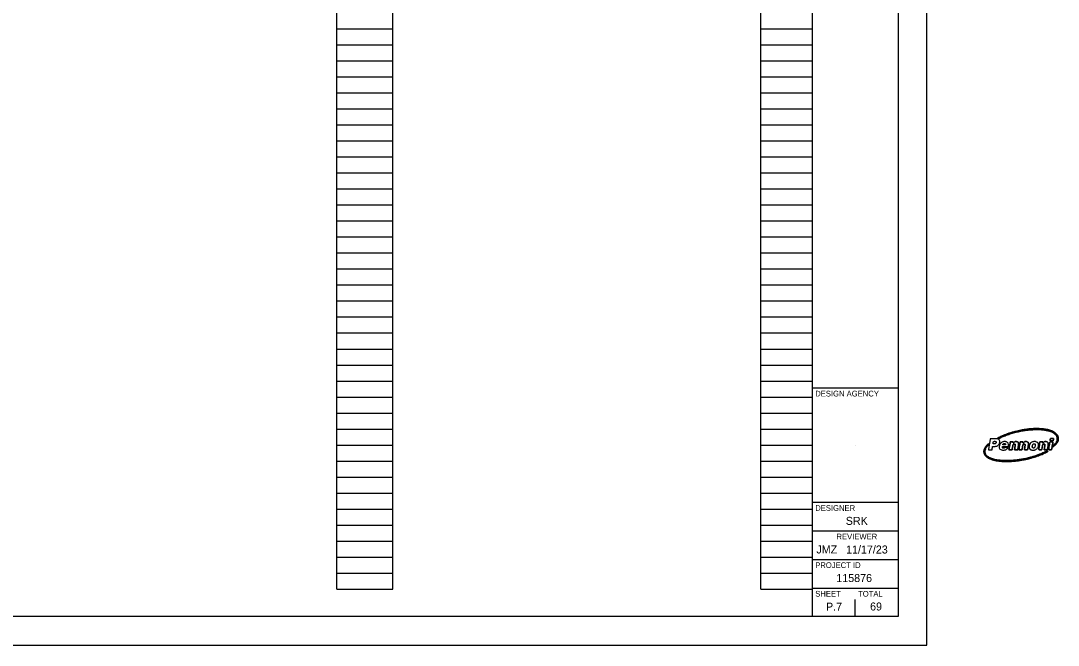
# Model space of a CAD drawing. Extents: x 0 to 36.3, y 0 to 22.
# Drawn here: x 18.15 to 36.3, y 0 to 10.92 of the extents above; entities that cross this region are included whole.
import ezdxf

# ---------------------------------------------------------------- set-up
doc = ezdxf.new("R2010")
doc.units = 0
for name, color, linetype in [('SH_Border', 7, 'Continuous'), ('SH_Cut_Line', 7, 'Continuous'), ('SH_Data', 7, 'Continuous')]:
    doc.layers.add(name, color=color, linetype=linetype)

msp = doc.modelspace()

# ---------------------------------------------------------------- linework, layer by layer
at = {"layer": 'SH_Border'}
for p, q in [((32, 0.5), (32, 21.5)), ((32, 4.5), (33.5, 4.5)), ((35.381, 3.503), (35.331, 3.503)), ((32, 2.5), (33.5, 2.5)), ((32, 2), (33.5, 2)), ((32, 1.5), (33.5, 1.5)), ((32, 1), (33.5, 1))]:
    msp.add_line(p, q, dxfattribs=at)
msp.add_lwpolyline([(1.5, 21.5), (33.5, 21.5), (33.5, 0.5), (1.5, 0.5)], close=True, dxfattribs=at)
for points, degree in [([(35.24, 3.621), (35.247, 3.619), (35.253, 3.616), (35.259, 3.615), (35.261, 3.614), (35.264, 3.614), (35.266, 3.615), (35.295, 3.629), (35.323, 3.643), (35.352, 3.655), (35.393, 3.673), (35.436, 3.688), (35.479, 3.701), (35.521, 3.714), (35.563, 3.725), (35.606, 3.734), (35.646, 3.743), (35.686, 3.751), (35.726, 3.756), (35.758, 3.76), (35.79, 3.764), (35.822, 3.767), (35.847, 3.769), (35.873, 3.77), (35.898, 3.771), (35.953, 3.772), (36.008, 3.77), (36.063, 3.762), (36.092, 3.758), (36.122, 3.752), (36.15, 3.742), (36.186, 3.731), (36.219, 3.717), (36.247, 3.691), (36.262, 3.678), (36.274, 3.661), (36.279, 3.641), (36.284, 3.624), (36.286, 3.607), (36.283, 3.589), (36.279, 3.569), (36.269, 3.552), (36.257, 3.536), (36.245, 3.521), (36.231, 3.508), (36.216, 3.495), (36.214, 3.494), (36.213, 3.492), (36.212, 3.49), (36.211, 3.485), (36.21, 3.479), (36.209, 3.473), (36.209, 3.471), (36.208, 3.469), (36.208, 3.465), (36.232, 3.485), (36.255, 3.505), (36.273, 3.529), (36.282, 3.54), (36.29, 3.553), (36.295, 3.566), (36.302, 3.585), (36.302, 3.604), (36.3, 3.623), (36.296, 3.658), (36.28, 3.685), (36.254, 3.708), (36.23, 3.728), (36.203, 3.741), (36.173, 3.752), (36.136, 3.766), (36.098, 3.774), (36.059, 3.779), (36.024, 3.784), (35.989, 3.787), (35.953, 3.788), (35.897, 3.789), (35.841, 3.787), (35.785, 3.781), (35.754, 3.777), (35.723, 3.773), (35.692, 3.768), (35.647, 3.761), (35.602, 3.752), (35.558, 3.74), (35.497, 3.725), (35.438, 3.707), (35.379, 3.684), (35.339, 3.669), (35.299, 3.651), (35.26, 3.631), (35.253, 3.628), (35.247, 3.625), (35.24, 3.621)], 3), ([(35.24, 3.621), (35.247, 3.625), (35.253, 3.628), (35.26, 3.631), (35.299, 3.651), (35.339, 3.669), (35.379, 3.684), (35.438, 3.707), (35.497, 3.725), (35.558, 3.74), (35.602, 3.752), (35.647, 3.761), (35.692, 3.768), (35.723, 3.773), (35.754, 3.777), (35.785, 3.781), (35.841, 3.787), (35.897, 3.789), (35.953, 3.788), (35.989, 3.787), (36.024, 3.784), (36.059, 3.779), (36.098, 3.774), (36.136, 3.766), (36.173, 3.752), (36.203, 3.741), (36.23, 3.728), (36.254, 3.708), (36.28, 3.685), (36.296, 3.658), (36.3, 3.623), (36.302, 3.604), (36.302, 3.585), (36.295, 3.566), (36.29, 3.553), (36.282, 3.54), (36.273, 3.529), (36.255, 3.505), (36.232, 3.485), (36.208, 3.465), (36.208, 3.469), (36.209, 3.471), (36.209, 3.473), (36.21, 3.479), (36.211, 3.485), (36.212, 3.49), (36.213, 3.492), (36.214, 3.494), (36.216, 3.495), (36.231, 3.508), (36.245, 3.521), (36.257, 3.536), (36.269, 3.552), (36.279, 3.569), (36.283, 3.589), (36.286, 3.607), (36.284, 3.624), (36.279, 3.641), (36.274, 3.661), (36.262, 3.678), (36.247, 3.691), (36.219, 3.717), (36.186, 3.731), (36.15, 3.742), (36.122, 3.752), (36.092, 3.758), (36.063, 3.762), (36.008, 3.77), (35.953, 3.772), (35.898, 3.771), (35.873, 3.77), (35.847, 3.769), (35.822, 3.767), (35.79, 3.764), (35.758, 3.76), (35.726, 3.756), (35.686, 3.751), (35.646, 3.743), (35.606, 3.734), (35.563, 3.725), (35.521, 3.714), (35.479, 3.701), (35.436, 3.688), (35.393, 3.673), (35.352, 3.655), (35.323, 3.643), (35.295, 3.629), (35.266, 3.615), (35.264, 3.614), (35.261, 3.614), (35.259, 3.615), (35.253, 3.616), (35.247, 3.619), (35.24, 3.621)], 3), ([(36.128, 3.392), (36.128, 3.392), (36.128, 3.393), (36.128, 3.393), (36.118, 3.393), (36.108, 3.393), (36.098, 3.393), (36.096, 3.393), (36.093, 3.392), (36.091, 3.391), (36.053, 3.372), (36.015, 3.355), (35.976, 3.34), (35.918, 3.317), (35.859, 3.298), (35.799, 3.283), (35.756, 3.271), (35.713, 3.262), (35.669, 3.254), (35.644, 3.25), (35.619, 3.246), (35.594, 3.242), (35.569, 3.239), (35.543, 3.236), (35.518, 3.234), (35.493, 3.232), (35.469, 3.23), (35.445, 3.23), (35.417, 3.229), (35.389, 3.228), (35.361, 3.229), (35.33, 3.231), (35.299, 3.233), (35.268, 3.236), (35.23, 3.24), (35.192, 3.248), (35.156, 3.259), (35.124, 3.269), (35.094, 3.282), (35.067, 3.302), (35.051, 3.314), (35.036, 3.329), (35.027, 3.348), (35.015, 3.374), (35.016, 3.4), (35.027, 3.427), (35.036, 3.45), (35.05, 3.47), (35.067, 3.488), (35.072, 3.494), (35.078, 3.5), (35.078, 3.509), (35.079, 3.514), (35.08, 3.52), (35.081, 3.526), (35.08, 3.525), (35.079, 3.525), (35.078, 3.524), (35.069, 3.514), (35.059, 3.505), (35.05, 3.494), (35.03, 3.472), (35.015, 3.448), (35.006, 3.419), (35.002, 3.402), (35, 3.385), (35.003, 3.368), (35.008, 3.341), (35.023, 3.319), (35.042, 3.301), (35.065, 3.28), (35.092, 3.266), (35.12, 3.254), (35.167, 3.235), (35.217, 3.225), (35.267, 3.219), (35.297, 3.216), (35.329, 3.214), (35.36, 3.212), (35.402, 3.211), (35.444, 3.211), (35.486, 3.215), (35.521, 3.217), (35.555, 3.221), (35.589, 3.225), (35.62, 3.229), (35.65, 3.234), (35.681, 3.239), (35.735, 3.249), (35.789, 3.261), (35.842, 3.276), (35.887, 3.289), (35.932, 3.304), (35.976, 3.321), (36.019, 3.338), (36.061, 3.356), (36.102, 3.377), (36.111, 3.382), (36.119, 3.387), (36.128, 3.392)], 3), ([(36.128, 3.392), (36.119, 3.387), (36.111, 3.382), (36.102, 3.377), (36.061, 3.356), (36.019, 3.338), (35.976, 3.321), (35.932, 3.304), (35.887, 3.289), (35.842, 3.276), (35.789, 3.261), (35.735, 3.249), (35.681, 3.239), (35.65, 3.234), (35.62, 3.229), (35.589, 3.225), (35.555, 3.221), (35.521, 3.217), (35.486, 3.215), (35.444, 3.211), (35.402, 3.211), (35.36, 3.212), (35.329, 3.214), (35.297, 3.216), (35.267, 3.219), (35.217, 3.225), (35.167, 3.235), (35.12, 3.254), (35.092, 3.266), (35.065, 3.28), (35.042, 3.301), (35.023, 3.319), (35.008, 3.341), (35.003, 3.368), (35, 3.385), (35.002, 3.402), (35.006, 3.419), (35.015, 3.448), (35.03, 3.472), (35.05, 3.494), (35.059, 3.505), (35.069, 3.514), (35.078, 3.524), (35.079, 3.525), (35.08, 3.525), (35.081, 3.526), (35.08, 3.52), (35.079, 3.514), (35.078, 3.509), (35.078, 3.5), (35.072, 3.494), (35.067, 3.488), (35.05, 3.47), (35.036, 3.45), (35.027, 3.427), (35.016, 3.4), (35.015, 3.374), (35.027, 3.348), (35.036, 3.329), (35.051, 3.314), (35.067, 3.302), (35.094, 3.282), (35.124, 3.269), (35.156, 3.259), (35.192, 3.248), (35.23, 3.24), (35.268, 3.236), (35.299, 3.233), (35.33, 3.231), (35.361, 3.229), (35.389, 3.228), (35.417, 3.229), (35.445, 3.23), (35.469, 3.23), (35.493, 3.232), (35.518, 3.234), (35.543, 3.236), (35.569, 3.239), (35.594, 3.242), (35.619, 3.246), (35.644, 3.25), (35.669, 3.254), (35.713, 3.262), (35.756, 3.271), (35.799, 3.283), (35.859, 3.298), (35.918, 3.317), (35.976, 3.34), (36.015, 3.355), (36.053, 3.372), (36.091, 3.391), (36.093, 3.392), (36.096, 3.393), (36.098, 3.393), (36.108, 3.393), (36.118, 3.393), (36.128, 3.393), (36.128, 3.393), (36.128, 3.392), (36.128, 3.392)], 3), ([(35.252, 3.602), (35.239, 3.608), (35.226, 3.61), (35.212, 3.61), (35.18, 3.611), (35.148, 3.61), (35.117, 3.61), (35.115, 3.61), (35.114, 3.61), (35.113, 3.608), (35.109, 3.586), (35.106, 3.565), (35.102, 3.543), (35.096, 3.509), (35.09, 3.474), (35.084, 3.439), (35.082, 3.432), (35.081, 3.424), (35.08, 3.417)], 3), ([(35.08, 3.417), (35.081, 3.417), (35.081, 3.417), (35.082, 3.417), (35.101, 3.417), (35.121, 3.417), (35.14, 3.417), (35.143, 3.417), (35.143, 3.418), (35.143, 3.42), (35.145, 3.431), (35.147, 3.442), (35.149, 3.454), (35.151, 3.461), (35.152, 3.469), (35.153, 3.477)], 3), ([(35.153, 3.477), (35.161, 3.477), (35.168, 3.477), (35.175, 3.477), (35.188, 3.477), (35.201, 3.477), (35.213, 3.48), (35.23, 3.483), (35.245, 3.49), (35.257, 3.502), (35.272, 3.518), (35.278, 3.537), (35.278, 3.559), (35.279, 3.578), (35.27, 3.593), (35.252, 3.602)], 3), ([(35.161, 3.522), (35.164, 3.536), (35.166, 3.55), (35.168, 3.563), (35.169, 3.564), (35.17, 3.565), (35.171, 3.565), (35.182, 3.565), (35.194, 3.567), (35.205, 3.563), (35.215, 3.56), (35.219, 3.554), (35.217, 3.543)], 3), ([(35.217, 3.543), (35.215, 3.531), (35.206, 3.523), (35.193, 3.522), (35.183, 3.522), (35.172, 3.522), (35.161, 3.522)], 3), ([(35.433, 3.508), (35.429, 3.533), (35.416, 3.55), (35.392, 3.557), (35.379, 3.562), (35.365, 3.562), (35.352, 3.561), (35.33, 3.558), (35.311, 3.549), (35.295, 3.532), (35.281, 3.517), (35.273, 3.5), (35.271, 3.479), (35.268, 3.45), (35.28, 3.426), (35.309, 3.417), (35.325, 3.412), (35.342, 3.411), (35.358, 3.414), (35.376, 3.416), (35.392, 3.422), (35.406, 3.434), (35.414, 3.441), (35.42, 3.449), (35.424, 3.459)], 3), ([(35.424, 3.459), (35.407, 3.459), (35.39, 3.459), (35.373, 3.458), (35.372, 3.458), (35.371, 3.457), (35.37, 3.457), (35.366, 3.454), (35.362, 3.45), (35.358, 3.448), (35.341, 3.442), (35.324, 3.451), (35.325, 3.47), (35.325, 3.474), (35.326, 3.475), (35.33, 3.475), (35.362, 3.475), (35.394, 3.475), (35.427, 3.475), (35.428, 3.475), (35.43, 3.475), (35.432, 3.475)], 3), ([(35.331, 3.503), (35.332, 3.515), (35.342, 3.525), (35.354, 3.527), (35.36, 3.528), (35.366, 3.528), (35.371, 3.525), (35.379, 3.521), (35.383, 3.513), (35.381, 3.503)], 3), ([(35.432, 3.475), (35.434, 3.486), (35.435, 3.497), (35.433, 3.508)], 2), ([(35.439, 3.416), (35.439, 3.415), (35.44, 3.415), (35.441, 3.415), (35.458, 3.415), (35.475, 3.415), (35.492, 3.415), (35.494, 3.415), (35.494, 3.416), (35.495, 3.418), (35.496, 3.426), (35.497, 3.435), (35.499, 3.443), (35.502, 3.46), (35.505, 3.478), (35.509, 3.495), (35.511, 3.505), (35.515, 3.513), (35.525, 3.515), (35.538, 3.519), (35.552, 3.516), (35.55, 3.497), (35.548, 3.482), (35.545, 3.468), (35.543, 3.454), (35.541, 3.441), (35.538, 3.428), (35.536, 3.416), (35.537, 3.415), (35.537, 3.415), (35.538, 3.415), (35.555, 3.415), (35.572, 3.415), (35.589, 3.415), (35.591, 3.415), (35.592, 3.416), (35.592, 3.419), (35.596, 3.442), (35.601, 3.466), (35.605, 3.49), (35.607, 3.502), (35.609, 3.515), (35.607, 3.527), (35.605, 3.543), (35.596, 3.554), (35.58, 3.558), (35.559, 3.564), (35.539, 3.56), (35.522, 3.545), (35.518, 3.542), (35.514, 3.538), (35.51, 3.535), (35.512, 3.542), (35.513, 3.549), (35.514, 3.557), (35.498, 3.557), (35.481, 3.557), (35.465, 3.556), (35.464, 3.556), (35.463, 3.555), (35.463, 3.554), (35.462, 3.55), (35.461, 3.545), (35.461, 3.541), (35.455, 3.511), (35.45, 3.48), (35.445, 3.45), (35.443, 3.438), (35.441, 3.427), (35.439, 3.416)], 3), ([(35.439, 3.416), (35.441, 3.427), (35.443, 3.438), (35.445, 3.45), (35.45, 3.48), (35.455, 3.511), (35.461, 3.541), (35.461, 3.545), (35.462, 3.55), (35.463, 3.554), (35.463, 3.555), (35.464, 3.556), (35.465, 3.556), (35.481, 3.557), (35.498, 3.557), (35.514, 3.557), (35.513, 3.549), (35.512, 3.542), (35.51, 3.535), (35.514, 3.538), (35.518, 3.542), (35.522, 3.545), (35.539, 3.56), (35.559, 3.564), (35.58, 3.558), (35.596, 3.554), (35.605, 3.543), (35.607, 3.527), (35.609, 3.515), (35.607, 3.502), (35.605, 3.49), (35.601, 3.466), (35.596, 3.442), (35.592, 3.419), (35.592, 3.416), (35.591, 3.415), (35.589, 3.415), (35.572, 3.415), (35.555, 3.415), (35.538, 3.415), (35.537, 3.415), (35.537, 3.415), (35.536, 3.416), (35.538, 3.428), (35.541, 3.441), (35.543, 3.454), (35.545, 3.468), (35.548, 3.482), (35.55, 3.497), (35.552, 3.516), (35.538, 3.519), (35.525, 3.515), (35.515, 3.513), (35.511, 3.505), (35.509, 3.495), (35.505, 3.478), (35.502, 3.46), (35.499, 3.443), (35.497, 3.435), (35.496, 3.426), (35.495, 3.418), (35.494, 3.416), (35.494, 3.415), (35.492, 3.415), (35.475, 3.415), (35.458, 3.415), (35.441, 3.415), (35.44, 3.415), (35.439, 3.415), (35.439, 3.416)], 3), ([(35.612, 3.416), (35.612, 3.415), (35.612, 3.415), (35.613, 3.415), (35.63, 3.415), (35.647, 3.415), (35.665, 3.415), (35.666, 3.415), (35.667, 3.417), (35.668, 3.418), (35.671, 3.435), (35.674, 3.452), (35.677, 3.469), (35.679, 3.479), (35.68, 3.49), (35.683, 3.5), (35.687, 3.513), (35.699, 3.519), (35.712, 3.516), (35.718, 3.515), (35.721, 3.511), (35.722, 3.505), (35.723, 3.502), (35.723, 3.499), (35.723, 3.496), (35.721, 3.485), (35.719, 3.473), (35.717, 3.462), (35.715, 3.447), (35.712, 3.431), (35.709, 3.416), (35.71, 3.415), (35.71, 3.415), (35.71, 3.415), (35.727, 3.415), (35.745, 3.415), (35.762, 3.415), (35.763, 3.415), (35.765, 3.417), (35.765, 3.418), (35.769, 3.441), (35.773, 3.463), (35.777, 3.485), (35.779, 3.497), (35.781, 3.509), (35.781, 3.522), (35.781, 3.537), (35.775, 3.55), (35.759, 3.556), (35.739, 3.564), (35.719, 3.562), (35.701, 3.55), (35.695, 3.545), (35.689, 3.54), (35.683, 3.535), (35.685, 3.543), (35.686, 3.549), (35.687, 3.557), (35.671, 3.557), (35.655, 3.557), (35.639, 3.557), (35.636, 3.557), (35.636, 3.555), (35.636, 3.553), (35.632, 3.529), (35.627, 3.505), (35.623, 3.481), (35.619, 3.46), (35.616, 3.438), (35.612, 3.416)], 3), ([(35.612, 3.416), (35.616, 3.438), (35.619, 3.46), (35.623, 3.481), (35.627, 3.505), (35.632, 3.529), (35.636, 3.553), (35.636, 3.555), (35.636, 3.557), (35.639, 3.557), (35.655, 3.557), (35.671, 3.557), (35.687, 3.557), (35.686, 3.549), (35.685, 3.543), (35.683, 3.535), (35.689, 3.54), (35.695, 3.545), (35.701, 3.55), (35.719, 3.562), (35.739, 3.564), (35.759, 3.556), (35.775, 3.55), (35.781, 3.537), (35.781, 3.522), (35.781, 3.509), (35.779, 3.497), (35.777, 3.485), (35.773, 3.463), (35.769, 3.441), (35.765, 3.418), (35.765, 3.417), (35.763, 3.415), (35.762, 3.415), (35.745, 3.415), (35.727, 3.415), (35.71, 3.415), (35.71, 3.415), (35.71, 3.415), (35.709, 3.416), (35.712, 3.431), (35.715, 3.447), (35.717, 3.462), (35.719, 3.473), (35.721, 3.485), (35.723, 3.496), (35.723, 3.499), (35.723, 3.502), (35.722, 3.505), (35.721, 3.511), (35.718, 3.515), (35.712, 3.516), (35.699, 3.519), (35.687, 3.513), (35.683, 3.5), (35.68, 3.49), (35.679, 3.479), (35.677, 3.469), (35.674, 3.452), (35.671, 3.435), (35.668, 3.418), (35.667, 3.417), (35.666, 3.415), (35.665, 3.415), (35.647, 3.415), (35.63, 3.415), (35.613, 3.415), (35.612, 3.415), (35.612, 3.415), (35.612, 3.416)], 3), ([(35.955, 3.508), (35.953, 3.53), (35.942, 3.545), (35.922, 3.554), (35.903, 3.562), (35.883, 3.562), (35.863, 3.558), (35.839, 3.553), (35.82, 3.541), (35.806, 3.52), (35.805, 3.518), (35.804, 3.515), (35.803, 3.513), (35.802, 3.511), (35.801, 3.509), (35.8, 3.507), (35.795, 3.496), (35.792, 3.484), (35.792, 3.472), (35.792, 3.47), (35.792, 3.467), (35.792, 3.465), (35.792, 3.457), (35.794, 3.45), (35.797, 3.444), (35.797, 3.443), (35.798, 3.441), (35.798, 3.44), (35.799, 3.439), (35.8, 3.438), (35.8, 3.437), (35.803, 3.434), (35.805, 3.43), (35.809, 3.427), (35.811, 3.426), (35.813, 3.424), (35.815, 3.423), (35.815, 3.422), (35.816, 3.422), (35.817, 3.422), (35.818, 3.421), (35.819, 3.42), (35.82, 3.42), (35.822, 3.419), (35.824, 3.418), (35.826, 3.417), (35.837, 3.412), (35.849, 3.411), (35.861, 3.41)], 3), ([(35.848, 3.471), (35.849, 3.487), (35.851, 3.501), (35.86, 3.513), (35.865, 3.519), (35.872, 3.523), (35.88, 3.523), (35.889, 3.523), (35.895, 3.52), (35.897, 3.511), (35.898, 3.505), (35.899, 3.498), (35.899, 3.491)], 3), ([(35.899, 3.491), (35.898, 3.481), (35.895, 3.471), (35.89, 3.462), (35.884, 3.452), (35.874, 3.447), (35.864, 3.449), (35.857, 3.45), (35.852, 3.453), (35.85, 3.459), (35.849, 3.464), (35.848, 3.469), (35.848, 3.471)], 3), ([(35.861, 3.41), (35.868, 3.411), (35.875, 3.412), (35.882, 3.413), (35.901, 3.416), (35.918, 3.425), (35.931, 3.439), (35.949, 3.459), (35.956, 3.482), (35.955, 3.508)], 3), ([(35.982, 3.556), (35.974, 3.509), (35.966, 3.462), (35.958, 3.415), (35.977, 3.415), (35.995, 3.415), (36.013, 3.415), (36.016, 3.43), (36.018, 3.444), (36.021, 3.458), (36.023, 3.471), (36.025, 3.484), (36.028, 3.496), (36.031, 3.51), (36.041, 3.517), (36.054, 3.517), (36.063, 3.516), (36.068, 3.511), (36.069, 3.503), (36.069, 3.5), (36.069, 3.497), (36.069, 3.494), (36.066, 3.475), (36.062, 3.456), (36.059, 3.437), (36.058, 3.43), (36.057, 3.423), (36.055, 3.415), (36.074, 3.415), (36.092, 3.415), (36.111, 3.415), (36.111, 3.417), (36.111, 3.418), (36.111, 3.419), (36.115, 3.44), (36.119, 3.462), (36.123, 3.483), (36.125, 3.497), (36.128, 3.51), (36.127, 3.525), (36.126, 3.541), (36.117, 3.553), (36.101, 3.558), (36.076, 3.565), (36.055, 3.559), (36.036, 3.541), (36.034, 3.539), (36.032, 3.537), (36.03, 3.535), (36.03, 3.535), (36.03, 3.535), (36.03, 3.536), (36.031, 3.542), (36.032, 3.549), (36.033, 3.556), (36.016, 3.556), (35.999, 3.556), (35.982, 3.556)], 3), ([(35.982, 3.556), (35.999, 3.556), (36.016, 3.556), (36.033, 3.556), (36.032, 3.549), (36.031, 3.542), (36.03, 3.536), (36.03, 3.535), (36.03, 3.535), (36.03, 3.535), (36.032, 3.537), (36.034, 3.539), (36.036, 3.541), (36.055, 3.559), (36.076, 3.565), (36.101, 3.558), (36.117, 3.553), (36.126, 3.541), (36.127, 3.525), (36.128, 3.51), (36.125, 3.497), (36.123, 3.483), (36.119, 3.462), (36.115, 3.44), (36.111, 3.419), (36.111, 3.418), (36.111, 3.417), (36.111, 3.415), (36.092, 3.415), (36.074, 3.415), (36.055, 3.415), (36.057, 3.423), (36.058, 3.43), (36.059, 3.437), (36.062, 3.456), (36.066, 3.475), (36.069, 3.494), (36.069, 3.497), (36.069, 3.5), (36.069, 3.503), (36.068, 3.511), (36.063, 3.516), (36.054, 3.517), (36.041, 3.517), (36.031, 3.51), (36.028, 3.496), (36.025, 3.484), (36.023, 3.471), (36.021, 3.458), (36.018, 3.444), (36.016, 3.43), (36.013, 3.415), (35.995, 3.415), (35.977, 3.415), (35.958, 3.415), (35.966, 3.462), (35.974, 3.509), (35.982, 3.556)], 3), ([(36.185, 3.417), (36.167, 3.417), (36.149, 3.417), (36.13, 3.417), (36.138, 3.464), (36.146, 3.51), (36.154, 3.557), (36.173, 3.557), (36.191, 3.557), (36.21, 3.557), (36.202, 3.51), (36.193, 3.464), (36.185, 3.417)], 3), ([(36.185, 3.417), (36.193, 3.464), (36.202, 3.51), (36.21, 3.557), (36.191, 3.557), (36.173, 3.557), (36.154, 3.557), (36.146, 3.51), (36.138, 3.464), (36.13, 3.417), (36.149, 3.417), (36.167, 3.417), (36.185, 3.417)], 3), ([(36.22, 3.615), (36.218, 3.603), (36.216, 3.591), (36.213, 3.578), (36.213, 3.577), (36.212, 3.576), (36.211, 3.576), (36.193, 3.576), (36.176, 3.576), (36.158, 3.576), (36.159, 3.586), (36.161, 3.595), (36.163, 3.604), (36.163, 3.606), (36.164, 3.609), (36.164, 3.611), (36.164, 3.615), (36.165, 3.615), (36.169, 3.615), (36.185, 3.615), (36.2, 3.615), (36.216, 3.615), (36.217, 3.615), (36.218, 3.615), (36.22, 3.615)], 3), ([(36.22, 3.615), (36.218, 3.615), (36.217, 3.615), (36.216, 3.615), (36.2, 3.615), (36.185, 3.615), (36.169, 3.615), (36.165, 3.615), (36.164, 3.615), (36.164, 3.611), (36.164, 3.609), (36.163, 3.606), (36.163, 3.604), (36.161, 3.595), (36.159, 3.586), (36.158, 3.576), (36.176, 3.576), (36.193, 3.576), (36.211, 3.576), (36.212, 3.576), (36.213, 3.577), (36.213, 3.578), (36.216, 3.591), (36.218, 3.603), (36.22, 3.615)], 3)]:
    msp.add_open_spline(points, degree=degree, dxfattribs=at)
at = {"layer": 'SH_Cut_Line'}
msp.add_lwpolyline([(0, 0), (34, 0), (34, 22), (0, 22)], close=True, dxfattribs=at)
at = {"layer": 'SH_Data'}
for p, q in [((23.68, 0.98), (23.68, 21.14)), ((24.66, 0.98), (24.66, 21.14)), ((31.1, 0.98), (31.1, 21.14)), ((32, 0.98), (32, 21.14)), ((23.68, 10.78), (24.66, 10.78)), ((31.1, 10.78), (32, 10.78)), ((23.68, 10.5), (24.66, 10.5)), ((31.1, 10.5), (32, 10.5)), ((23.68, 10.22), (24.66, 10.22)), ((31.1, 10.22), (32, 10.22)), ((23.68, 9.94), (24.66, 9.94)), ((31.1, 9.94), (32, 9.94)), ((23.68, 9.66), (24.66, 9.66)), ((31.1, 9.66), (32, 9.66)), ((23.68, 9.38), (24.66, 9.38)), ((31.1, 9.38), (32, 9.38)), ((23.68, 9.1), (24.66, 9.1)), ((31.1, 9.1), (32, 9.1)), ((23.68, 8.82), (24.66, 8.82)), ((31.1, 8.82), (32, 8.82)), ((23.68, 8.54), (24.66, 8.54)), ((31.1, 8.54), (32, 8.54)), ((23.68, 8.26), (24.66, 8.26)), ((31.1, 8.26), (32, 8.26)), ((23.68, 7.98), (24.66, 7.98)), ((31.1, 7.98), (32, 7.98)), ((23.68, 7.7), (24.66, 7.7)), ((31.1, 7.7), (32, 7.7)), ((23.68, 7.42), (24.66, 7.42)), ((31.1, 7.42), (32, 7.42)), ((23.68, 7.14), (24.66, 7.14)), ((31.1, 7.14), (32, 7.14)), ((23.68, 6.86), (24.66, 6.86)), ((31.1, 6.86), (32, 6.86)), ((23.68, 6.58), (24.66, 6.58)), ((31.1, 6.58), (32, 6.58)), ((23.68, 6.3), (24.66, 6.3)), ((31.1, 6.3), (32, 6.3)), ((23.68, 6.02), (24.66, 6.02)), ((31.1, 6.02), (32, 6.02)), ((23.68, 5.74), (24.66, 5.74)), ((31.1, 5.74), (32, 5.74)), ((23.68, 5.46), (24.66, 5.46)), ((31.1, 5.46), (32, 5.46)), ((23.68, 5.18), (24.66, 5.18)), ((31.1, 5.18), (32, 5.18)), ((23.68, 4.9), (24.66, 4.9)), ((31.1, 4.9), (32, 4.9)), ((23.68, 4.62), (24.66, 4.62)), ((31.1, 4.62), (32, 4.62)), ((23.68, 4.34), (24.66, 4.34)), ((31.1, 4.34), (32, 4.34)), ((23.68, 4.06), (24.66, 4.06)), ((31.1, 4.06), (32, 4.06)), ((23.68, 3.78), (24.66, 3.78)), ((31.1, 3.78), (32, 3.78)), ((23.68, 3.5), (24.66, 3.5)), ((31.1, 3.5), (32, 3.5)), ((32.75, 3.5), (32.75, 3.5)), ((23.68, 3.22), (24.66, 3.22)), ((31.1, 3.22), (32, 3.22)), ((23.68, 2.94), (24.66, 2.94)), ((31.1, 2.94), (32, 2.94)), ((23.68, 2.66), (24.66, 2.66)), ((31.1, 2.66), (32, 2.66)), ((23.68, 2.38), (24.66, 2.38)), ((31.1, 2.38), (32, 2.38)), ((23.68, 2.1), (24.66, 2.1)), ((31.1, 2.1), (32, 2.1)), ((23.68, 1.82), (24.66, 1.82)), ((31.1, 1.82), (32, 1.82)), ((23.68, 1.54), (24.66, 1.54)), ((31.1, 1.54), (32, 1.54)), ((23.68, 1.26), (24.66, 1.26)), ((31.1, 1.26), (32, 1.26)), ((23.68, 0.98), (24.66, 0.98)), ((31.1, 0.98), (32, 0.98)), ((32.75, 0.5), (32.75, 0.8)), ((32.375, 0.675), (32.375, 0.675))]:
    msp.add_line(p, q, dxfattribs=at)

# ---------------------------------------------------------------- texts
for s, height, p in [('DESIGN AGENCY', 0.1, (32.05, 4.35)), ('DESIGNER', 0.1, (32.05, 2.35)), ('SRK', 0.14, (32.585, 2.105)), ('REVIEWER', 0.1, (32.422, 1.85)), ('JMZ', 0.14, (32.071, 1.605)), ('11/17/23', 0.14, (32.59, 1.604)), ('PROJECT ID', 0.1, (32.05, 1.35)), ('115876', 0.14, (32.419, 1.105)), ('SHEET', 0.1, (32.05, 0.85)), ('TOTAL', 0.1, (32.8, 0.85)), ('P.7', 0.14, (32.239, 0.605)), ('69', 0.14, (33.01, 0.608))]:
    msp.add_text(s, height=height, dxfattribs=at).set_placement(p)

doc.saveas('drawing.dxf')
